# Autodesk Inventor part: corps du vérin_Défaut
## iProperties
Shininess: 64.0
Length Units: 11269
Angle Units: 11279
Time Units: 11290
Mass Units: 11283
Length Display Precision: 3
Angle Display Precision: 2
Compacted: True
Part Number: corps du vérin_Défaut
Document SubType Name: Modeling
Created: 2006-11
Material: Par défaut
Designer: profs_sti
Density: 0.0
Volumn: 0.0
Area: 0.0
PropertySet Name: Model Information
Control State: 0
Master: False
Checked Out: False
Author: profs_sti
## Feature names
1. Base1
